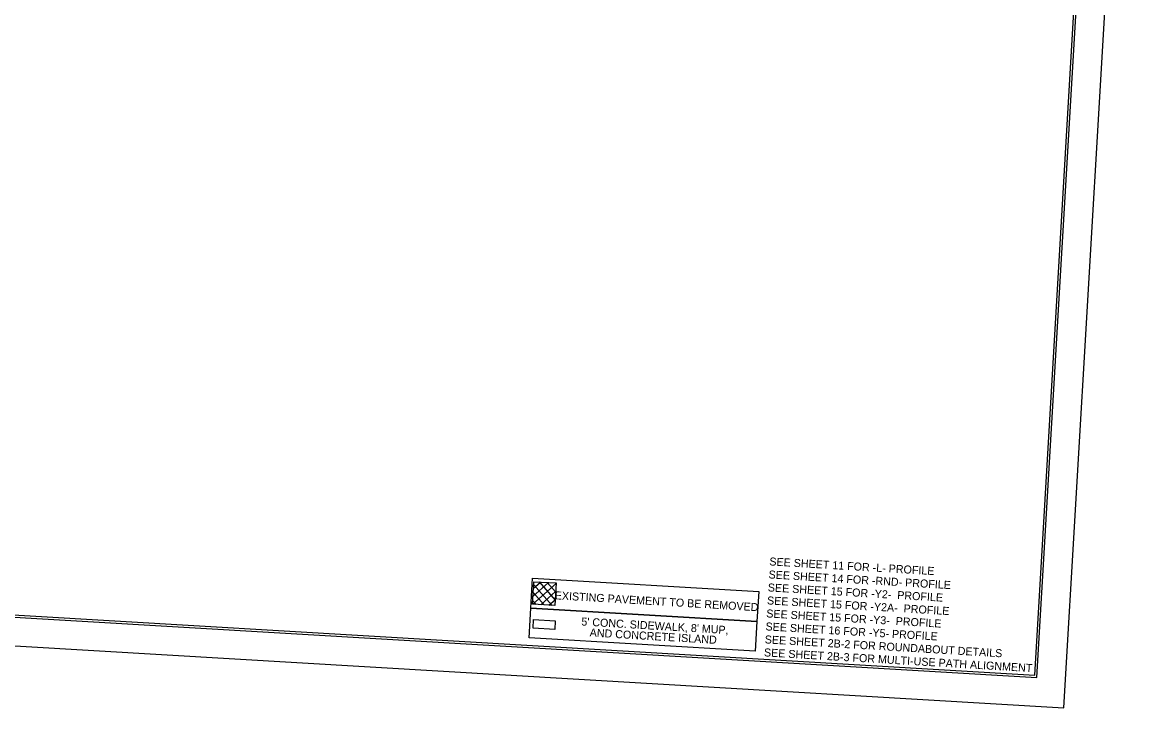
# Model space of a CAD drawing. Extents: x 2012145 to 2014096, y 444445 to 445643.
# Drawn here: x 2013121 to 2014096, y 444445 to 445044 of the extents above; entities that cross this region are included whole.
import ezdxf

# ---------------------------------------------------------------- set-up
doc = ezdxf.new("R2010")
doc.units = 0
for name, color, linetype in [('Exist PHM Road to be Removed Shape', 7, 'Continuous'), ('Old_Level_1', 7, 'Continuous'), ('Prop DSN Text', 7, 'Continuous'), ('Prop Shade Medium', 7, 'Continuous'), ('Sheet Clip Boundary CELL', 7, 'Continuous'), ('Sheet Plan And Profile CELL', 7, 'Continuous'), ('Sheet Plot Border Outside CELL', 7, 'Continuous')]:
    doc.layers.add(name, color=color, linetype=linetype)

msp = doc.modelspace()

# ---------------------------------------------------------------- linework, layer by layer
at = {"layer": 'Exist PHM Road to be Removed Shape'}
for p, q in [((2013566.98, 444535.35), (2013587.37, 444553.46)), ((2013567.02, 444542.07), (2013580.87, 444554.37)), ((2013567.44, 444549.13), (2013573.81, 444554.79)), ((2013567.65, 444552.81), (2013584.07, 444534.34)), ((2013572.52, 444554.87), (2013586.52, 444539.1)), ((2013579.58, 444554.45), (2013586.94, 444546.16)), ((2013586.64, 444554.03), (2013587.36, 444553.22)), ((2013567.24, 444545.75), (2013577.01, 444534.76)), ((2013574.04, 444534.93), (2013586.95, 444546.41)), ((2013581.1, 444534.52), (2013586.54, 444539.35)), ((2013566.82, 444538.69), (2013569.95, 444535.17))]:
    msp.add_line(p, q, dxfattribs=at)
msp.add_lwpolyline([(2013567.79, 444555.14), (2013587.4, 444553.99), (2013586.24, 444534.21), (2013566.63, 444535.37)], close=True, dxfattribs=at)
at = {"layer": 'Old_Level_1'}
for points in [[(2013566.8, 444558.14), (2013764.65, 444546.47), (2013763.12, 444520.46), (2013565.27, 444532.12)], [(2013565.27, 444532.12), (2013763.12, 444520.46), (2013761.58, 444494.44), (2013563.74, 444506.11)]]:
    msp.add_lwpolyline(points, close=True, dxfattribs=at)
at = {"layer": 'Prop Shade Medium'}
msp.add_lwpolyline([(2013567.67, 444522), (2013586.68, 444520.88), (2013586.23, 444513.27), (2013567.22, 444514.39)], close=True, dxfattribs=at)
at = {"layer": 'Sheet Clip Boundary CELL'}
msp.add_lwpolyline([(2013668.15, 445541.27), (2012675.49, 445599.79), (2012666.5, 445450.87), (2012644.05, 445070.04), (2012629.92, 444830.46), (2012620.01, 444659.47), (2012673.15, 444619.9), (2012617.31, 444617.99), (2012613.72, 444555.61), (2014006.01, 444473.54), (2014041.96, 445083.42), (2013915.76, 445258.44), (2013612.37, 445329.9), (2013615.96, 445390.93), (2013652.41, 445436.93), (2013664.23, 445474.69)], close=True, dxfattribs=at)
at = {"layer": 'Sheet Plan And Profile CELL'}
msp.add_lwpolyline([(2014069.67, 445519.6), (2012572.27, 445607.87), (2012510.48, 444559.69), (2014007.88, 444471.42)], close=True, dxfattribs=at)
at = {"layer": 'Sheet Plot Border Outside CELL'}
msp.add_lwpolyline([(2012334.32, 444545.03), (2014031.37, 444445), (2014096.1, 445543.09), (2012399.05, 445643.13)], close=True, dxfattribs=at)

# ---------------------------------------------------------------- texts
at = {"layer": 'Prop DSN Text'}
for s, p in [('SEE SHEET 11 FOR -L- PROFILE', (2013773.77, 444569.4)), ('SEE SHEET 14 FOR -RND- PROFILE', (2013773.1, 444558.04)), ('SEE SHEET 15 FOR -Y2-  PROFILE', (2013772.43, 444546.69)), ('EXISTING PAVEMENT TO BE REMOVED', (2013586.08, 444539.78)), ('SEE SHEET 15 FOR -Y2A-  PROFILE', (2013771.76, 444535.33)), ('SEE SHEET 15 FOR -Y3-  PROFILE', (2013771.09, 444523.97)), ("5' CONC. SIDEWALK, 8' MUP,", (2013609.34, 444516.9)), ('AND CONCRETE ISLAND', (2013616.63, 444507.28)), ('SEE SHEET 16 FOR -Y5- PROFILE', (2013770.42, 444512.62)), ('SEE SHEET 2B-2 FOR ROUNDABOUT DETAILS', (2013769.75, 444501.26)), ('SEE SHEET 2B-3 FOR MULTI-USE PATH ALIGNMENT', (2013769.08, 444489.91))]:
    msp.add_text(s, height=7, rotation=356.62643, dxfattribs=at).set_placement(p)

doc.saveas('drawing.dxf')
